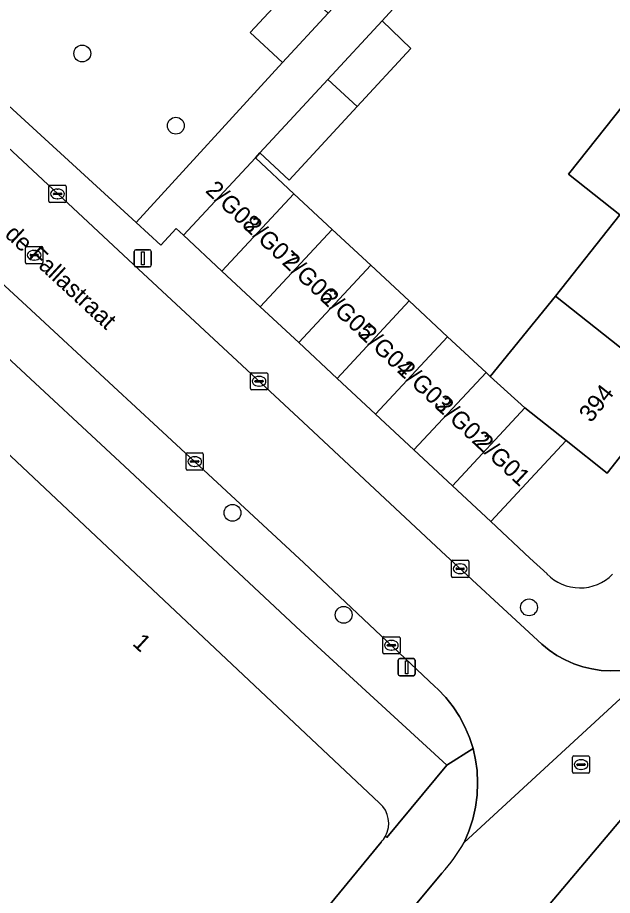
# Model space of a CAD drawing. Extents: x 159217 to 160349, y 381246 to 382172.
# Drawn here: x 159848.1 to 159882.6, y 381535.4 to 381586.3 of the extents above; entities that cross this region are included whole.
import ezdxf

# ---------------------------------------------------------------- set-up
doc = ezdxf.new("R2010")
doc.units = 0
for name, color, linetype in [('IMGEO_Boom', 7, 'Continuous'), ('IMGEO_Erf', 7, 'Continuous'), ('IMGEO_Kolk', 7, 'Continuous'), ('IMGEO_Lichtmast', 7, 'Continuous'), ('IMGEO_Openbare_ruimte_label', 7, 'Continuous'), ('IMGEO_Pand', 7, 'Continuous'), ('IMGEO_Pand_nummerreeks', 7, 'Continuous'), ('IMGEO_Rijbaan_lokaal_open', 7, 'Continuous'), ('IMGEO_Rioolput', 7, 'Continuous'), ('IMGEO_Voetpad_open', 7, 'Continuous')]:
    doc.layers.add(name, color=color, linetype=linetype)

msp = doc.modelspace()

# ---------------------------------------------------------------- linework, layer by layer
at = {"layer": 'IMGEO_Boom'}
for centre in [(159851.87, 381584.25), (159857.3, 381580.06), (159860.586, 381557.609), (159877.795, 381552.127), (159867.039, 381551.693)]:
    msp.add_circle(centre, 0.489, dxfattribs=at)
at = {"layer": 'IMGEO_Erf'}
for points in [[(159891.859, 381656.228), (159840.577, 381600.766), (159843.162, 381598.335), (159836.759, 381591.155), (159854.989, 381574.45), (159863.492, 381583.729), (159861.622, 381585.458), (159864.266, 381588.318), (159866.785, 381591.042), (159868.655, 381589.313), (159872.741, 381593.716), (159870.871, 381595.445), (159873.515, 381598.305), (159876.034, 381601.029), (159877.904, 381599.3), (159881.961, 381603.666), (159884.605, 381606.525), (159884.405, 381606.71), (159882.189, 381604.314), (159880.519, 381605.858), (159882.735, 381608.254), (159885.254, 381610.979)], [(159870.098, 381587.04), (159869.264, 381586.138), (159870.933, 381584.54), (159867.816, 381581.169), (159863.878, 381576.908), (159862.182, 381578.476), (159861.918, 381578.189), (159864.148, 381576.115), (159866.379, 381574.042), (159868.609, 381571.968), (159870.84, 381569.894), (159873.07, 381567.82), (159875.301, 381565.747), (159875.549, 381565.516), (159879.33, 381570.17), (159883.066, 381574.887), (159880.087, 381577.246), (159883.815, 381581.954)], [(159854.322, 381560.319), (159847.497, 381566.647), (159844.752, 381563.687), (159869.124, 381540.774)], [(159884.402, 381562.529), (159882.328, 381559.909), (159879.945, 381561.796), (159875.577, 381557.103), (159877.851, 381554.987), (159878.839, 381554.068)], [(159869.461, 381538.851), (159869.542, 381538.774), (159873.023, 381542.974), (159864.549, 381550.739), (159854.322, 381560.319)]]:
    msp.add_lwpolyline(points, dxfattribs=at)
for centre, radius, start, end in [((159880.749, 381555.909), 2.653, 223.9385, 315.3676), ((159868.095, 381539.603), 1.559, 331.1795, 48.7004)]:
    msp.add_arc(centre, radius, start, end, dxfattribs=at)
at = {"layer": 'IMGEO_Kolk'}
for p, q in [((159849.933, 381575.677), (159849.933, 381576.529)), ((159850.008, 381576.603), (159850.86, 381576.603)), ((159850.934, 381576.529), (159850.934, 381575.677)), ((159850.192, 381576.097), (159850.192, 381576.109)), ((159850.63, 381576.06), (159850.232, 381576.06)), ((159850.235, 381576.146), (159850.633, 381576.146)), ((159850.421, 381576.383), (159850.446, 381576.383)), ((159850.676, 381576.109), (159850.676, 381576.097)), ((159850.86, 381575.603), (159850.008, 381575.603)), ((159850.444, 381575.823), (159850.419, 381575.823)), ((159861.705, 381565.736), (159862.557, 381565.736)), ((159861.63, 381564.81), (159861.63, 381565.662)), ((159861.889, 381565.23), (159861.889, 381565.242)), ((159862.327, 381565.193), (159861.929, 381565.193)), ((159861.932, 381565.279), (159862.33, 381565.279)), ((159862.118, 381565.516), (159862.143, 381565.516)), ((159862.373, 381565.242), (159862.373, 381565.23)), ((159862.631, 381565.662), (159862.631, 381564.81)), ((159862.557, 381564.736), (159861.705, 381564.736)), ((159862.141, 381564.956), (159862.116, 381564.956)), ((159857.894, 381560.155), (159857.894, 381561.007)), ((159857.969, 381561.081), (159858.821, 381561.081)), ((159858.196, 381560.624), (159858.594, 381560.624)), ((159858.382, 381560.861), (159858.407, 381560.861)), ((159858.895, 381561.007), (159858.895, 381560.155)), ((159858.153, 381560.575), (159858.153, 381560.587)), ((159858.591, 381560.538), (159858.193, 381560.538)), ((159858.405, 381560.301), (159858.38, 381560.301)), ((159858.637, 381560.587), (159858.637, 381560.575)), ((159858.821, 381560.081), (159857.969, 381560.081)), ((159873.296, 381553.936), (159873.296, 381554.788)), ((159873.371, 381554.862), (159874.223, 381554.862)), ((159873.784, 381554.642), (159873.809, 381554.642)), ((159874.297, 381554.788), (159874.297, 381553.936)), ((159873.555, 381554.356), (159873.555, 381554.368)), ((159873.993, 381554.319), (159873.595, 381554.319)), ((159873.598, 381554.405), (159873.996, 381554.405)), ((159873.807, 381554.082), (159873.782, 381554.082)), ((159874.039, 381554.368), (159874.039, 381554.356)), ((159874.223, 381553.862), (159873.371, 381553.862)), ((159869.384, 381550.426), (159870.236, 381550.426)), ((159869.309, 381549.5), (159869.309, 381550.352)), ((159869.568, 381549.92), (159869.568, 381549.932)), ((159869.611, 381549.969), (159870.009, 381549.969)), ((159869.797, 381550.206), (159869.822, 381550.206)), ((159870.052, 381549.932), (159870.052, 381549.92)), ((159870.31, 381550.352), (159870.31, 381549.5)), ((159870.236, 381549.426), (159869.384, 381549.426)), ((159870.006, 381549.883), (159869.608, 381549.883)), ((159869.82, 381549.646), (159869.795, 381549.646))]:
    msp.add_line(p, q, dxfattribs=at)
for points in [[(159849.933, 381575.677), (159849.933, 381576.529)], [(159850.008, 381576.603), (159850.86, 381576.603)], [(159850.934, 381576.529), (159850.934, 381575.677)], [(159850.86, 381575.603), (159850.008, 381575.603)], [(159861.705, 381565.736), (159862.557, 381565.736)], [(159861.63, 381564.81), (159861.63, 381565.662)], [(159862.631, 381565.662), (159862.631, 381564.81)], [(159862.557, 381564.736), (159861.705, 381564.736)], [(159857.894, 381560.155), (159857.894, 381561.007)], [(159857.969, 381561.081), (159858.821, 381561.081)], [(159858.895, 381561.007), (159858.895, 381560.155)], [(159858.821, 381560.081), (159857.969, 381560.081)], [(159873.296, 381553.936), (159873.296, 381554.788)], [(159873.371, 381554.862), (159874.223, 381554.862)], [(159874.297, 381554.788), (159874.297, 381553.936)], [(159874.223, 381553.862), (159873.371, 381553.862)], [(159869.384, 381550.426), (159870.236, 381550.426)], [(159869.309, 381549.5), (159869.309, 381550.352)], [(159870.31, 381550.352), (159870.31, 381549.5)], [(159870.236, 381549.426), (159869.384, 381549.426)]]:
    msp.add_lwpolyline(points, dxfattribs=at)
for centre, radius, start, end in [((159850.01, 381576.527), 0.0765, 91.552, 178.448), ((159850.01, 381576.527), 0.0765, 91.552, 178.448), ((159850.858, 381576.527), 0.0765, 1.552, 88.448), ((159850.858, 381576.527), 0.0765, 1.552, 88.448), ((159850.232, 381576.106), 0.0403, 85.8775, 175.7526), ((159850.229, 381576.096), 0.0366, 178.938, 274.7102), ((159850.633, 381576.103), 0.043, 264.8664, 352.4533), ((159850.637, 381576.108), 0.0386, 1.7309, 96.639), ((159850.01, 381575.679), 0.0765, 181.552, 268.448), ((159850.01, 381575.679), 0.0765, 181.552, 268.448), ((159850.858, 381575.679), 0.0765, 271.552, 358.448), ((159850.858, 381575.679), 0.0765, 271.552, 358.448), ((159861.707, 381565.66), 0.0765, 91.552, 178.448), ((159861.707, 381565.66), 0.0765, 91.552, 178.448), ((159862.555, 381565.66), 0.0765, 1.552, 88.448), ((159862.555, 381565.66), 0.0765, 1.552, 88.448), ((159861.929, 381565.239), 0.0403, 85.8775, 175.7526), ((159861.926, 381565.229), 0.0366, 178.938, 274.7102), ((159862.33, 381565.236), 0.043, 264.8664, 352.4533), ((159862.334, 381565.241), 0.0386, 1.7309, 96.639), ((159861.707, 381564.812), 0.0765, 181.552, 268.448), ((159861.707, 381564.812), 0.0765, 181.552, 268.448), ((159862.555, 381564.812), 0.0765, 271.552, 358.448), ((159862.555, 381564.812), 0.0765, 271.552, 358.448), ((159857.971, 381561.005), 0.0765, 91.552, 178.448), ((159857.971, 381561.005), 0.0765, 91.552, 178.448), ((159858.193, 381560.584), 0.0403, 85.8775, 175.7526), ((159858.598, 381560.586), 0.0386, 1.7309, 96.639), ((159858.819, 381561.005), 0.0765, 1.552, 88.448), ((159858.819, 381561.005), 0.0765, 1.552, 88.448), ((159857.971, 381560.157), 0.0765, 181.552, 268.448), ((159857.971, 381560.157), 0.0765, 181.552, 268.448), ((159858.19, 381560.574), 0.0366, 178.938, 274.7102), ((159858.594, 381560.581), 0.043, 264.8664, 352.4533), ((159858.819, 381560.157), 0.0765, 271.552, 358.448), ((159858.819, 381560.157), 0.0765, 271.552, 358.448), ((159873.373, 381554.786), 0.0765, 91.552, 178.448), ((159873.373, 381554.786), 0.0765, 91.552, 178.448), ((159874.221, 381554.786), 0.0765, 1.552, 88.448), ((159874.221, 381554.786), 0.0765, 1.552, 88.448), ((159873.595, 381554.365), 0.0403, 85.8775, 175.7526), ((159873.592, 381554.355), 0.0366, 178.938, 274.7102), ((159873.996, 381554.362), 0.043, 264.8664, 352.4533), ((159874, 381554.367), 0.0386, 1.7309, 96.639), ((159873.373, 381553.938), 0.0765, 181.552, 268.448), ((159873.373, 381553.938), 0.0765, 181.552, 268.448), ((159874.221, 381553.938), 0.0765, 271.552, 358.448), ((159874.221, 381553.938), 0.0765, 271.552, 358.448), ((159869.386, 381550.35), 0.0765, 91.552, 178.448), ((159869.386, 381550.35), 0.0765, 91.552, 178.448), ((159870.234, 381550.35), 0.0765, 1.552, 88.448), ((159870.234, 381550.35), 0.0765, 1.552, 88.448), ((159869.608, 381549.929), 0.0403, 85.8775, 175.7526), ((159869.605, 381549.919), 0.0366, 178.938, 274.7102), ((159870.009, 381549.926), 0.043, 264.8664, 352.4533), ((159870.013, 381549.931), 0.0386, 1.7309, 96.639), ((159869.386, 381549.502), 0.0765, 181.552, 268.448), ((159869.386, 381549.502), 0.0765, 181.552, 268.448), ((159870.234, 381549.502), 0.0765, 271.552, 358.448), ((159870.234, 381549.502), 0.0765, 271.552, 358.448)]:
    msp.add_arc(centre, radius, start, end, dxfattribs=at)
for centre, major_axis, ratio, start_param, end_param in [((159850.42, 381576.103), (-0.387, 0.002), 0.722429, 4.712389, 7.853982), ((159850.445, 381576.103), (-0.39, 0.002), 0.717154, 1.570796, 4.712389), ((159862.117, 381565.236), (-0.387, 0.002), 0.722429, 4.712389, 7.853982), ((159862.142, 381565.236), (-0.39, 0.002), 0.717154, 1.570796, 4.712389), ((159858.381, 381560.581), (-0.387, 0.002), 0.722429, 4.712389, 7.853982), ((159858.406, 381560.581), (-0.39, 0.002), 0.717154, 1.570796, 4.712389), ((159873.783, 381554.362), (-0.387, 0.002), 0.722429, 4.712389, 7.853982), ((159873.808, 381554.362), (-0.39, 0.002), 0.717154, 1.570796, 4.712389), ((159869.796, 381549.926), (-0.387, 0.002), 0.722429, 4.712389, 7.853982), ((159869.821, 381549.926), (-0.39, 0.002), 0.717154, 1.570796, 4.712389)]:
    msp.add_ellipse(centre, major_axis=major_axis, ratio=ratio, start_param=start_param, end_param=end_param, dxfattribs=at)
at = {"layer": 'IMGEO_Lichtmast'}
for p, q in [((159854.985, 381572.865), (159855.775, 381572.865)), ((159855.775, 381572.865), (159854.985, 381572.865)), ((159854.885, 381571.965), (159854.885, 381572.765)), ((159854.885, 381572.765), (159854.885, 381571.965)), ((159855.875, 381572.765), (159855.875, 381571.965)), ((159855.875, 381571.965), (159855.875, 381572.765)), ((159855.775, 381571.865), (159854.985, 381571.865)), ((159854.985, 381571.865), (159855.775, 381571.865)), ((159870.198, 381548.255), (159870.198, 381549.055)), ((159870.198, 381549.055), (159870.198, 381548.255)), ((159870.298, 381549.155), (159871.088, 381549.155)), ((159871.088, 381549.155), (159870.298, 381549.155)), ((159871.188, 381549.055), (159871.188, 381548.255)), ((159871.188, 381548.255), (159871.188, 381549.055)), ((159871.088, 381548.155), (159870.298, 381548.155)), ((159870.298, 381548.155), (159871.088, 381548.155))]:
    msp.add_line(p, q, dxfattribs=at)
for points in [[(159855.305, 381572.74), (159855.455, 381572.74), (159855.455, 381571.99), (159855.305, 381571.99), (159855.305, 381572.74)], [(159870.618, 381549.03), (159870.768, 381549.03), (159870.768, 381548.28), (159870.618, 381548.28), (159870.618, 381549.03)]]:
    msp.add_lwpolyline(points, dxfattribs=at)
for centre, start, end in [((159854.985, 381572.765), 90, 180), ((159854.985, 381572.765), 90, 180), ((159855.775, 381572.765), 0, 90), ((159855.775, 381572.765), 360, 90), ((159854.985, 381571.965), 180, 270), ((159854.985, 381571.965), 180, 270), ((159855.775, 381571.965), 270, 0), ((159855.775, 381571.965), 270, 0), ((159870.298, 381549.055), 90, 180), ((159870.298, 381549.055), 90, 180), ((159871.088, 381549.055), 0, 90), ((159871.088, 381549.055), 360, 90), ((159870.298, 381548.255), 180, 270), ((159870.298, 381548.255), 180, 270), ((159871.088, 381548.255), 270, 0), ((159871.088, 381548.255), 270, 0)]:
    msp.add_arc(centre, 0.1, start, end, dxfattribs=at)
at = {"layer": 'IMGEO_Pand'}
for points in [[(159866.136, 381586.589), (159864.266, 381588.318), (159861.622, 381585.458), (159863.492, 381583.729)], [(159869.264, 381586.138), (159866.12, 381582.737), (159867.816, 381581.169), (159870.933, 381584.54)], [(159867.816, 381581.169), (159866.12, 381582.737), (159862.182, 381578.476), (159863.878, 381576.908)], [(159894.807, 381573.261), (159886.794, 381579.595), (159883.815, 381581.954), (159880.087, 381577.246), (159883.066, 381574.887), (159889.911, 381569.476), (159891.878, 381571.961), (159893.046, 381571.036)], [(159864.148, 381576.115), (159861.918, 381578.189), (159857.742, 381573.702), (159859.971, 381571.627)], [(159862.201, 381569.552), (159866.379, 381574.042), (159864.148, 381576.115), (159859.971, 381571.627)], [(159887.316, 381563.857), (159889.083, 381566.089), (159887.944, 381566.991), (159889.911, 381569.476), (159883.066, 381574.887), (159879.33, 381570.17)], [(159868.609, 381571.968), (159866.379, 381574.042), (159862.201, 381569.552), (159864.43, 381567.477)], [(159866.66, 381565.402), (159870.84, 381569.894), (159868.609, 381571.968), (159864.43, 381567.477)], [(159868.889, 381563.328), (159873.07, 381567.82), (159870.84, 381569.894), (159866.66, 381565.402)], [(159887.316, 381563.857), (159879.33, 381570.17), (159875.549, 381565.516), (159877.547, 381563.69), (159879.945, 381561.796), (159882.328, 381559.909), (159884.402, 381562.529), (159885.547, 381561.623)], [(159873.07, 381567.82), (159868.889, 381563.328), (159871.118, 381561.253), (159875.301, 381565.747)], [(159877.547, 381563.69), (159875.549, 381565.516), (159875.301, 381565.747), (159871.118, 381561.253), (159873.348, 381559.178)], [(159879.945, 381561.796), (159877.547, 381563.69), (159873.348, 381559.178), (159875.577, 381557.103)]]:
    msp.add_lwpolyline(points, close=True, dxfattribs=at)
msp.add_lwpolyline([(159869.124, 381540.774), (159844.752, 381563.687), (159841.359, 381560.013), (159825.528, 381542.87), (159836.336, 381532.851), (159847.835, 381522.19), (159848.51, 381521.565), (159852.177, 381518.166), (159855.252, 381521.539), (159869.206, 381538.504)], dxfattribs=at)
for centre, radius, start, end in [((159868.095, 381539.603), 1.559, 331.1795, 48.7004), ((159867.891, 381539.738), 1.803, 316.8303, 330.5476)]:
    msp.add_arc(centre, radius, start, end, dxfattribs=at)
at = {"layer": 'IMGEO_Rijbaan_lokaal_open'}
for points in [[(159883.078, 381548.459), (159882.531, 381548.441), (159881.985, 381548.472), (159881.443, 381548.552), (159880.911, 381548.68), (159880.392, 381548.855), (159879.891, 381549.076), (159879.412, 381549.34), (159878.959, 381549.646), (159878.534, 381549.992), (159876.296, 381552.057), (159872.694, 381555.382), (159864.692, 381562.858), (159855.141, 381571.732), (159846.923, 381579.367)], [(159841.851, 381575.861), (159848.634, 381569.604), (159853.689, 381564.941), (159856.274, 381562.547), (159864.737, 381554.71), (159872.339, 381547.543), (159872.512, 381547.381), (159872.975, 381546.892), (159873.393, 381546.364), (159873.762, 381545.801), (159874.079, 381545.206), (159874.342, 381544.586), (159874.549, 381543.945), (159874.697, 381543.288), (159874.777, 381542.669), (159874.81, 381541.955), (159874.779, 381541.241), (159874.684, 381540.533), (159874.526, 381539.836), (159874.306, 381539.156), (159874.027, 381538.498), (159886.532, 381549.994)], [(159888.171, 381545.168), (159894.5, 381550.196), (159910.193, 381562.267), (159913.544, 381564.89), (159910.683, 381568.58), (159897.902, 381558.679), (159893.425, 381555.305), (159891.463, 381553.82), (159886.532, 381549.994), (159874.027, 381538.498)], [(159852.476, 381503.945), (159858.653, 381510.302), (159861.681, 381513.94), (159864.009, 381516.737), (159866.993, 381520.322), (159871.369, 381525.65), (159873.971, 381528.818), (159877.985, 381533.705), (159885.307, 381542.394)], [(159872.735, 381536.717), (159861.86, 381523.669), (159860.521, 381522.062), (159853.538, 381513.604), (159848.394, 381508.173)]]:
    msp.add_lwpolyline(points, dxfattribs=at)
msp.add_arc((159866.541, 381542.569), 8.521, 316.6235, 331.4596, dxfattribs=at)
at = {"layer": 'IMGEO_Rioolput'}
for p, q in [((159848.579, 381572.123), (159848.579, 381572.975)), ((159848.654, 381573.049), (159849.506, 381573.049)), ((159849.067, 381572.829), (159849.092, 381572.829)), ((159849.58, 381572.975), (159849.58, 381572.123)), ((159848.838, 381572.543), (159848.838, 381572.555)), ((159849.276, 381572.506), (159848.878, 381572.506)), ((159848.881, 381572.592), (159849.279, 381572.592)), ((159849.322, 381572.555), (159849.322, 381572.543)), ((159849.506, 381572.049), (159848.654, 381572.049)), ((159849.09, 381572.269), (159849.065, 381572.269)), ((159880.313, 381542.58), (159880.313, 381543.432)), ((159880.388, 381543.506), (159881.24, 381543.506)), ((159881.314, 381543.432), (159881.314, 381542.58)), ((159880.572, 381543), (159880.572, 381543.012)), ((159881.01, 381542.963), (159880.612, 381542.963)), ((159880.615, 381543.049), (159881.013, 381543.049)), ((159880.801, 381543.286), (159880.826, 381543.286)), ((159881.056, 381543.012), (159881.056, 381543)), ((159881.24, 381542.506), (159880.388, 381542.506)), ((159880.824, 381542.726), (159880.799, 381542.726))]:
    msp.add_line(p, q, dxfattribs=at)
for points in [[(159848.579, 381572.123), (159848.579, 381572.975)], [(159848.654, 381573.049), (159849.506, 381573.049)], [(159849.58, 381572.975), (159849.58, 381572.123)], [(159849.506, 381572.049), (159848.654, 381572.049)], [(159880.313, 381542.58), (159880.313, 381543.432)], [(159880.388, 381543.506), (159881.24, 381543.506)], [(159881.314, 381543.432), (159881.314, 381542.58)], [(159881.24, 381542.506), (159880.388, 381542.506)]]:
    msp.add_lwpolyline(points, dxfattribs=at)
for centre, radius, start, end in [((159848.656, 381572.973), 0.0765, 91.552, 178.448), ((159848.656, 381572.973), 0.0765, 91.552, 178.448), ((159849.504, 381572.973), 0.0765, 1.552, 88.448), ((159849.504, 381572.973), 0.0765, 1.552, 88.448), ((159848.878, 381572.552), 0.0403, 85.8775, 175.7526), ((159848.875, 381572.542), 0.0366, 178.938, 274.7102), ((159849.279, 381572.549), 0.043, 264.8664, 352.4533), ((159849.283, 381572.554), 0.0386, 1.7309, 96.639), ((159848.656, 381572.125), 0.0765, 181.552, 268.448), ((159848.656, 381572.125), 0.0765, 181.552, 268.448), ((159849.504, 381572.125), 0.0765, 271.552, 358.448), ((159849.504, 381572.125), 0.0765, 271.552, 358.448), ((159880.39, 381543.43), 0.0765, 91.552, 178.448), ((159880.39, 381543.43), 0.0765, 91.552, 178.448), ((159881.238, 381543.43), 0.0765, 1.552, 88.448), ((159881.238, 381543.43), 0.0765, 1.552, 88.448), ((159880.612, 381543.009), 0.0403, 85.8775, 175.7526), ((159880.609, 381542.999), 0.0366, 178.938, 274.7102), ((159881.013, 381543.006), 0.043, 264.8664, 352.4533), ((159881.017, 381543.011), 0.0386, 1.7309, 96.639), ((159880.39, 381542.582), 0.0765, 181.552, 268.448), ((159880.39, 381542.582), 0.0765, 181.552, 268.448), ((159881.238, 381542.582), 0.0765, 271.552, 358.448), ((159881.238, 381542.582), 0.0765, 271.552, 358.448)]:
    msp.add_arc(centre, radius, start, end, dxfattribs=at)
for centre, major_axis, ratio, start_param, end_param in [((159849.066, 381572.549), (-0.387, 0.002), 0.722429, 4.712389, 7.853982), ((159849.091, 381572.549), (-0.39, 0.002), 0.717154, 1.570796, 4.712389), ((159880.8, 381543.006), (-0.387, 0.002), 0.722429, 4.712389, 7.853982), ((159880.825, 381543.006), (-0.39, 0.002), 0.717154, 1.570796, 4.712389)]:
    msp.add_ellipse(centre, major_axis=major_axis, ratio=ratio, start_param=start_param, end_param=end_param, dxfattribs=at)
at = {"layer": 'IMGEO_Voetpad_open'}
for points in [[(159884.605, 381606.525), (159881.961, 381603.666), (159877.904, 381599.3), (159875.385, 381596.576), (159872.741, 381593.716), (159868.655, 381589.313), (159866.136, 381586.589), (159863.492, 381583.729), (159854.989, 381574.45), (159856.438, 381573.122), (159857.324, 381574.089), (159857.742, 381573.702), (159861.918, 381578.189), (159862.182, 381578.476), (159866.12, 381582.737), (159869.264, 381586.138), (159870.098, 381587.04), (159870.936, 381587.946), (159874.106, 381591.375), (159877.303, 381594.834), (159881.122, 381599.028), (159884.335, 381602.443)], [(159836.759, 381591.155), (159835.569, 381589.866), (159840.646, 381585.172), (159843.803, 381582.252), (159846.923, 381579.367), (159855.141, 381571.732), (159864.692, 381562.858), (159872.694, 381555.382), (159876.296, 381552.057), (159878.534, 381549.992), (159878.959, 381549.646), (159879.412, 381549.34), (159879.891, 381549.076), (159880.392, 381548.855), (159880.911, 381548.68), (159881.443, 381548.552), (159881.985, 381548.472), (159882.531, 381548.441), (159883.078, 381548.459), (159883.095, 381548.46)], [(159878.839, 381554.068), (159877.851, 381554.987), (159875.577, 381557.103), (159873.348, 381559.178), (159871.118, 381561.253), (159868.889, 381563.328), (159866.66, 381565.402), (159864.43, 381567.477), (159862.201, 381569.552), (159859.971, 381571.627), (159857.742, 381573.702), (159857.324, 381574.089), (159856.438, 381573.122), (159854.989, 381574.45), (159836.759, 381591.155)], [(159829.458, 381583.371), (159845.603, 381568.403), (159846.62, 381567.46), (159847.497, 381566.647), (159854.322, 381560.319), (159864.549, 381550.739), (159873.023, 381542.974), (159874.549, 381543.945), (159874.342, 381544.586), (159874.079, 381545.206), (159873.762, 381545.801), (159873.393, 381546.364), (159872.975, 381546.892), (159872.512, 381547.381), (159872.339, 381547.543), (159864.737, 381554.71), (159856.274, 381562.547), (159853.689, 381564.941), (159848.634, 381569.604), (159841.851, 381575.861)], [(159874.027, 381538.498), (159874.306, 381539.156), (159874.526, 381539.836), (159874.684, 381540.533), (159874.779, 381541.241), (159874.81, 381541.955), (159874.777, 381542.669), (159874.697, 381543.288), (159874.549, 381543.945), (159873.023, 381542.974), (159869.542, 381538.774), (159869.461, 381538.851)], [(159886.028, 381543.216), (159885.307, 381542.394), (159877.985, 381533.705), (159873.971, 381528.818), (159871.369, 381525.65), (159866.993, 381520.322), (159864.009, 381516.737), (159861.681, 381513.94), (159858.653, 381510.302), (159852.476, 381503.945)], [(159869.206, 381538.504), (159855.252, 381521.539), (159852.177, 381518.166), (159848.924, 381514.815), (159846.789, 381512.616), (159844.346, 381510.071), (159842.053, 381507.683), (159841.734, 381507.351), (159839.902, 381505.617), (159839.744, 381505.468), (159837.066, 381503.655), (159836.436, 381503.183), (159832.06, 381500), (159829.328, 381498.013), (159823.713, 381493.928), (159818.579, 381490.194), (159817.956, 381489.745), (159815.615, 381488.127), (159814.734, 381487.519), (159806.144, 381481.325), (159805.174, 381480.604), (159800.034, 381476.898), (159796.728, 381474.339)], [(159830.472, 381494.77), (159834.595, 381497.652), (159837.953, 381500), (159838.633, 381500.471), (159841.86, 381502.709), (159842.416, 381503.135), (159844.347, 381504.612), (159847.98, 381507.736), (159848.394, 381508.173), (159853.538, 381513.604), (159860.521, 381522.062), (159861.86, 381523.669), (159872.735, 381536.717)]]:
    msp.add_lwpolyline(points, dxfattribs=at)
for centre, radius, start, end in [((159880.749, 381555.909), 2.653, 223.9385, 315.3676), ((159867.891, 381539.738), 1.803, 316.8303, 330.5476), ((159866.541, 381542.569), 8.521, 316.6235, 331.4596)]:
    msp.add_arc(centre, radius, start, end, dxfattribs=at)

# ---------------------------------------------------------------- texts
at = {"layer": 'IMGEO_Openbare_ruimte_label'}
msp.add_text('de Fallastraat', height=1, rotation=317.2291, dxfattribs=at).set_placement((159847.321, 381573.681))
at = {"layer": 'IMGEO_Pand_nummerreeks'}
for s, rotation, p in [('2/G08', 316.8476, (159858.966, 381576.242)), ('2/G07', 316.8476, (159861.189, 381574.159)), ('2/G06', 316.8476, (159863.414, 381572.073)), ('2/G05', 316.8476, (159865.638, 381569.987)), ('2/G04', 316.8476, (159867.863, 381567.901)), ('2/G03', 316.8476, (159870.088, 381565.816)), ('394', 51.6751, (159881.393, 381562.79)), ('2/G02', 316.8448, (159872.308, 381563.734)), ('2/G01', 316.8448, (159874.618, 381561.569)), ('1', 317.2058, (159854.73, 381549.978))]:
    msp.add_text(s, height=1, rotation=rotation, dxfattribs=at).set_placement(p)

doc.saveas('drawing.dxf')
